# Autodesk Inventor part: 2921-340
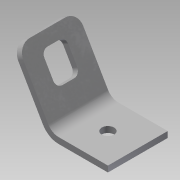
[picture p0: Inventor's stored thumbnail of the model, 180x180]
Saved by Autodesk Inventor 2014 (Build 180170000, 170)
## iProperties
Company: NHTSA/VRTC
Created: 2013-12
Part Number: 2921-340
Project: CHILD SIDE IMPACT SLED
Material: Steel, Mild
Description: TOP TETHER ANCHOR
Document SubType Name: Modeling
Designer: DW
Stock Number: PL 3.2 (1/8") x 31.8 (1 1/4") x 67.2 (2 5/8")
Density: 7.86 g/cm^3
Appearance: Steel
Mass: 47.1337 g
Surface Area: 46.1747 cm^2
Volume: 5.99666 cm^3
Title: Top Tether Anchor
Subject: Child Side Impact Sled
Author: Dave Walker
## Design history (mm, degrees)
sketch "Sketch1"
  geometry: L1 (-10.376, 3.175)-(15.875, 3.175); L2 (15.875, 3.175)-(15.875, 0); L3 (15.875, 0)-(-10.376, 0); L4 (-15.875, 6.35)-(-32.175, 34.583); L5 (-32.175, 34.583)-(-34.925, 32.996); L6 (-34.925, 32.996)-(-18.625, 4.762); A1 r 6.35 centre (-10.376, 9.525) between (-15.875, 6.35) and (-10.376, 3.175); A2 r 9.525 centre (-10.376, 9.525) between (-18.625, 4.762) and (-10.376, 0); 2 further points
  constraints: 12 end point, 4 point on circle, 4 tangent, 3 point on line, 2 centre point, 2 parallel, 2 perpendicular, 1 horizontal
  dimensions: "d0" = 31.75 distance of L2.end point (-15.875, 0); "d1" = 38.1 distance from line of point (-15.875, 0) L5; "d2" = 3.175 distance of L1.end L2.end; "d3" = 60 deg angle of L6 L3; "d4" = 3.175 distance between parallel lines of L4 L6 (= d2); "d5" = 15.875 distance from line of L2 point (0, 0); "d6" = 6.35 radius of A1; "d7" = 9.525 radius of A2
extrude "Extrusion1" new body sketch "Sketch1" stored distance "d8" = 31.75; taper "d9" = 0 deg
fillet "Fillet1" dims "d10" = 6.35
sketch "Sketch2"
  geometry: 2 further points
  constraints: 1 coincident
hole "Hole1" sketch "Sketch2" at (10.376, 15.875) diameter "d11" = 6.5278; stored, may be unused: countersink angle "d15" = 82 deg, drill point angle "d17" = 118 deg; dims "d12" = 19.05, "d13" = 19.05, "d14" = 4.7752, "d16" = 25.4
sketch "Sketch3"
  geometry: L1 (25.4, 32.601)-(6.35, 32.601) reference; L2 (12.7, 26.251)-(19.05, 26.251); L3 (22.225, 23.076)-(22.225, 13.551); L4 (19.05, 10.376)-(12.7, 10.376); L5 (9.525, 13.551)-(9.525, 23.076); A1 r 3.175 centre (12.7, 23.076) between (12.7, 26.251) and (9.525, 23.076); A2 r 3.175 centre (19.05, 23.076) between (22.225, 23.076) and (19.05, 26.251); A3 r 3.175 centre (12.7, 13.551) between (9.525, 13.551) and (12.7, 10.376); A4 r 3.175 centre (19.05, 13.551) between (19.05, 10.376) and (22.225, 13.551); 5 further points
  constraints: 8 end point, 8 point on circle, 8 tangent, 4 centre point, 4 point on line, 3 equal radius, 2 midpoint, 2 parallel, 1 horizontal, 1 perpendicular, 1 vertical alignment
  dimensions: "d18" = 6.35 distance between parallel lines of L2 L1; "d19" = 15.875 distance between parallel lines of L4 L2; "d20" = 12.7 distance of point (9.525, 26.251) point (22.225, 26.251); "d21" = 3.175 radius of A1
extrude "Extrusion2" cut sketch "Sketch3" stored distance "d22" = 31.75; taper "d23" = 0 deg
body "Solid1"
